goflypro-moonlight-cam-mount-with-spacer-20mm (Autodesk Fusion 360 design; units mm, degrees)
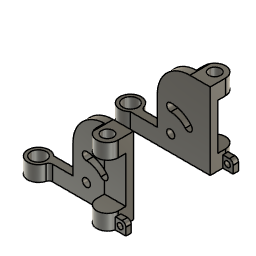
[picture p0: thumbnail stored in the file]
sketch "Skizze1" plane through (0, 0, 0) normal (0, 0, 1) x axis (1, 0, 0)
  line L1 (7.2, 0) -> (-7.2, 0)
  line L2 (7.2, 0) -> (7.2, -2)
  line L3 (-1, 0) -> (-1, 2)
  line L4 (12.8, 2) -> (-8.605, 2)
  line L5 (12.8, 2) -> (12.8, -2)
  line L6 (12.8, 0) -> (7.2, 0)
  line L7 (11, -2) -> (11, 2)
  line L8 (12.8, -2) -> (11, -2)
  circle C1 centre (-10, 0) radius 2
  circle C2 centre (10, -2) radius 1.55
  circle C3 centre (-10, 0) radius 2.8
  circle C4 centre (10, -2) radius 2.8
  point P6 (-7.2, 0)
  point P7 (7.2, -2)
  point P10 (-1, 0)
  point P12 (12.8, -2)
  point P14 (12.8, 0)
  point P15 (11, 2)
  concentric C1 C3
  concentric C2 C4
  coincident C3 P6
  horizontal L1
  coincident C4 P7
  tangent C4 L2
  perpendicular L1 L2
  perpendicular L1 L3
  coincident L1 P10
  coincident C4 P12
  tangent C4 L5
  perpendicular L4 L5
  midpoint L5 P14
  coincident L4 P15
  perpendicular L6 L7
  dimension "d1" diameter C1 = 4
  dimension "d2" diameter C2 = 3.1
  dimension "d3" diameter C3 = 5.6
  dimension "d4" diameter C4 = 5.6
extrude "Extrusion1" new body sketch "Skizze1" profile of C1 C3 L1 L3 L4 along normal blind 4 bodies "GoFlyPro - Moonlight-cam mount with spacer - left"
extrude "Extrusion5" new body sketch "Skizze1" profile of C2 C4 L2 L5 L6 L7 L8 along normal blind 4 bodies "GoFlyPro - Moonlight-cam mount with spacer-20mm - left"
extrude "Extrusion8" add sketch "Skizze1" profile of C4 L1 L3 L4 L5 L6 L7 along normal blind 20 bodies "GoFlyPro - Moonlight-cam mount with spacer - left"
sketch "Skizze2" plane through (0, 0, 0) normal (0, 1, 0) x axis (1, 0, 0)
  line L1 (7.2, 0) -> (-7.2, 0)
  line L2 (7.2, -4) -> (7.2, 0)
  line L3 (7.2, -20) -> (7.2, -4)
  line L4 (-1, -20) -> (7.2, -20)
  line L5 (-1, -4) -> (-1, -20)
  line L6 (-7.2, -4) -> (-1, -4)
  line L7 (-7.2, 0) -> (-7.2, -4)
  circle C1 centre (2.5, -4.25) radius 1.05
  circle C2 centre (2.5, -4.25) radius 4.95
  circle C3 centre (2.5, -4.25) radius 7.05
  circle C4 centre (2.5, -10.25) radius 1.05
  circle C5 centre (7.0963, -8.1067) radius 1.05
  concentric C1 C2
  concentric C2 C3
  dimension "d8" diameter C1 = 2.1
  dimension "d32" diameter C4 = 2.1
  dimension "d64" diameter C5 = 2.1
extrude "Extrusion2" cut sketch "Skizze2" profile of C1 C2 C3 C4 C5 L3 along normal blind 2
fillet "Abrundung12" radius 1
work_plane "Arbeitsebene" AlongDistance 12
sketch "Skizze3" plane through (0, 0, 20) normal (0, 0, 1) x axis (-1, 0, 0)
  line L1 (-12.8, -2) -> (-12.8, 2)
  line L2 (-7, -2) -> (-12.8, -2)
  line L3 (-7, 0) -> (-7, -2)
  line L4 (-7.2, 0) -> (-7, 0)
  line L5 (-11.9596, 0) -> (-7.2, 0)
  line L6 (1, 0) -> (1, -2)
  line L7 (-7.2, 0) -> (1, 0)
  line L8 (-12.8, 0) -> (-7.2, 0)
  line L9 (-12.8, -2) -> (-12.8, 0)
  line L10 (1, -2) -> (-12.8, -2)
  line L11 (-11.9596, 0) -> (-12.8, 0)
  line L12 (-12.8, 2) -> (-12.8, 0)
  line L13 (-8.0404, 0) -> (-7.2, 0)
  line L14 (-7.2, 2) -> (-7.2, 0)
  circle C1 centre (-10, 2) radius 1.55
  circle C2 centre (-10, 2) radius 2.8
  arc A1 centre (-10, 2) radius 2.8 clockwise from (-11.9596, 0) to (-12.8, 2)
  point P14 (-12.8, 0)
  point P16 (-12.8, 0)
  point P2 (-11.9596, 0)
  point P17 (-11.9596, 0)
  point P18 (-12.8, 0)
  point P3 (-12.8, 2)
  point P19 (-12.8, 2)
  point P13 (-7.2, 0)
  point P20 (-7.2, 0)
  point P21 (-8.0404, 0)
  point P22 (-7.2, 0)
  point P23 (-7.2, 2)
  concentric C1 C2
  coincident P14 P16
  coincident P2 P17
  coincident P14 P18
  coincident P3 P19
  coincident P13 P20
  coincident C2 P21
  coincident L5 P21
  coincident P13 P22
  coincident C2 P23
  tangent C2 L14
  dimension "d77" diameter C1 = 3.1
  dimension "d78" diameter C2 = 5.6
extrude "Extrusion10" add sketch "Skizze3" profile of L1 C1 C2 L5 A1 L8 L11 L12 L13 L14 against normal blind 4
extrude "Extrusion11" cut sketch "Skizze1" profile of C2 L7 L8 along normal blind 3.2
extrude "Extrusion12" cut sketch "Skizze3" profile of C1 against normal blind 3.2
fillet "Abrundung20" radius 8.5
sketch "Skizze4" plane through (0, 0, 0) normal (0, 0, 1) x axis (1, 0, 0)
  line L1 (12.5, -2.7) -> (15.5, -2.7)
  line L2 (12.5, -1.3) -> (12.5, -2.7)
  line L3 (15.5, -1.3) -> (12.5, -1.3)
  line L4 (15.5, -2.7) -> (15.5, -1.3)
  horizontal L1
  vertical L2
  horizontal L3
  vertical L4
extrude "Extrusion13" add sketch "Skizze4" along normal blind 3
sketch "Skizze5" plane through (0, -2.7, 0) normal (0, -1, 0) x axis (1, 0, 0)
  line L1 (12.7111, 0) -> (12.7111, 3)
  line L2 (15.5, 0) -> (12.7111, 0)
  line L3 (15.5, 3) -> (15.5, 0)
  line L4 (12.7111, 3) -> (15.5, 3)
  circle C1 centre (14, 1.5) radius 0.75
  dimension "d95" diameter C1 = 1.5
extrude "Extrusion14" cut sketch "Skizze5" profile of C1 against normal blind 1.4
fillet "Abrundung22" radius 1
mirror "Spiegeln" mirrorStitchTolerance 0.1 bodies "GoFlyPro - Moonlight-cam mount with spacer-20mm - right"
named bodies: "GoFlyPro - Moonlight-cam mount with spacer-20mm - left", "GoFlyPro - Moonlight-cam mount with spacer - left", "GoFlyPro - Moonlight-cam mount with spacer-20mm - right"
